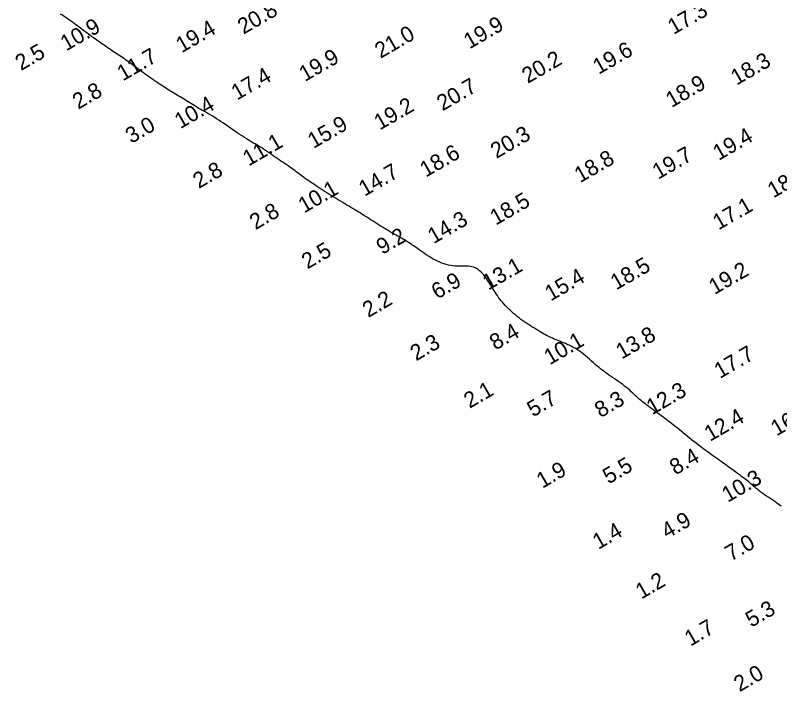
# Model space of a CAD drawing. Extents: x 3024098 to 3056816, y 418252 to 509144.
# Drawn here: x 3025732.3 to 3025973.9, y 428251.7 to 428465.6 of the extents above; entities that cross this region are included whole.
import ezdxf

# ---------------------------------------------------------------- set-up
doc = ezdxf.new("R2010")
doc.units = 0
doc.layers.add('V-CHAN-CONT-EL10', color=7, linetype='Continuous')
doc.layers.add('V-TOPO-SOUN-0911', color=7, linetype='Continuous')

msp = doc.modelspace()

# ---------------------------------------------------------------- linework, layer by layer
at = {"layer": 'V-CHAN-CONT-EL10'}
for points in [[(3025751.42, 428462.58), (3025750.91, 428462.96), (3025750.4, 428463.33), (3025749.87, 428463.71), (3025749.34, 428464.09), (3025748.8, 428464.46), (3025748.25, 428464.82), (3025747.7, 428465.18), (3025747.15, 428465.54), (3025746.59, 428465.88)], [(3025974.31, 428310.34), (3025973.87, 428310.68), (3025973.39, 428311.04), (3025972.87, 428311.42), (3025972.3, 428311.83), (3025971.68, 428312.24), (3025971.04, 428312.68), (3025970.39, 428313.12), (3025969.74, 428313.56), (3025969.1, 428313.99), (3025968.49, 428314.42), (3025967.91, 428314.84), (3025967.39, 428315.24), (3025966.91, 428315.62), (3025966.46, 428315.98), (3025966.04, 428316.34), (3025965.64, 428316.68), (3025965.26, 428317.02), (3025964.88, 428317.35), (3025964.49, 428317.68), (3025964.1, 428318.01), (3025963.69, 428318.34), (3025963.27, 428318.67), (3025962.85, 428319.01), (3025962.4, 428319.35), (3025961.95, 428319.69), (3025961.49, 428320.03), (3025961.02, 428320.38), (3025960.54, 428320.74), (3025960.04, 428321.1), (3025959.54, 428321.46), (3025959.03, 428321.83), (3025958.52, 428322.2), (3025957.99, 428322.57), (3025957.47, 428322.95), (3025956.94, 428323.33), (3025956.4, 428323.71), (3025955.87, 428324.09), (3025955.32, 428324.48), (3025954.76, 428324.89), (3025954.19, 428325.3), (3025953.6, 428325.72), (3025952.99, 428326.17), (3025952.35, 428326.63), (3025951.69, 428327.11), (3025951, 428327.6), (3025950.3, 428328.12), (3025949.59, 428328.65), (3025948.87, 428329.18), (3025948.14, 428329.73), (3025947.42, 428330.28), (3025946.7, 428330.84), (3025946, 428331.39), (3025945.31, 428331.95), (3025944.63, 428332.5), (3025943.97, 428333.04), (3025943.32, 428333.58), (3025942.68, 428334.1), (3025942.05, 428334.61), (3025941.44, 428335.1), (3025940.84, 428335.58), (3025940.25, 428336.04), (3025939.68, 428336.49), (3025939.11, 428336.92), (3025938.55, 428337.35), (3025938, 428337.76), (3025937.46, 428338.17), (3025936.93, 428338.57), (3025936.4, 428338.96), (3025935.88, 428339.35), (3025935.36, 428339.74), (3025934.85, 428340.12), (3025934.34, 428340.5), (3025933.84, 428340.87), (3025933.34, 428341.24), (3025932.85, 428341.6), (3025932.37, 428341.96), (3025931.89, 428342.31), (3025931.42, 428342.67), (3025930.96, 428343.02), (3025930.5, 428343.38), (3025930.05, 428343.74), (3025929.6, 428344.11), (3025929.17, 428344.5), (3025928.74, 428344.89), (3025928.31, 428345.29), (3025927.87, 428345.7), (3025927.43, 428346.13), (3025926.97, 428346.55), (3025926.49, 428346.99), (3025925.98, 428347.43), (3025925.44, 428347.88), (3025924.87, 428348.33), (3025924.26, 428348.78), (3025923.63, 428349.24), (3025922.98, 428349.69), (3025922.32, 428350.15), (3025921.66, 428350.6), (3025921, 428351.05), (3025920.36, 428351.49), (3025919.74, 428351.93), (3025919.13, 428352.37), (3025918.53, 428352.8), (3025917.94, 428353.25), (3025917.36, 428353.7), (3025916.78, 428354.17), (3025916.19, 428354.65), (3025915.6, 428355.16), (3025915, 428355.69), (3025914.38, 428356.24), (3025913.76, 428356.79), (3025913.13, 428357.35), (3025912.5, 428357.89), (3025911.86, 428358.42), (3025911.22, 428358.93), (3025910.57, 428359.4), (3025909.93, 428359.83), (3025909.28, 428360.22), (3025908.64, 428360.58), (3025908, 428360.91), (3025907.37, 428361.22), (3025906.75, 428361.5), (3025906.13, 428361.76), (3025905.52, 428362.01), (3025904.92, 428362.26), (3025904.33, 428362.49), (3025903.75, 428362.73), (3025903.18, 428362.96), (3025902.62, 428363.2), (3025902.05, 428363.45), (3025901.49, 428363.7), (3025900.94, 428363.97), (3025900.38, 428364.26), (3025899.82, 428364.55), (3025899.25, 428364.87), (3025898.69, 428365.19), (3025898.12, 428365.53), (3025897.54, 428365.88), (3025896.96, 428366.24), (3025896.37, 428366.6), (3025895.77, 428366.98), (3025895.16, 428367.36), (3025894.55, 428367.76), (3025893.93, 428368.16), (3025893.32, 428368.57), (3025892.71, 428369), (3025892.1, 428369.43), (3025891.5, 428369.88), (3025890.9, 428370.35), (3025890.32, 428370.82), (3025889.75, 428371.31), (3025889.19, 428371.8), (3025888.65, 428372.3), (3025888.13, 428372.8), (3025887.63, 428373.31), (3025887.15, 428373.81), (3025886.69, 428374.32), (3025886.25, 428374.82), (3025885.83, 428375.33), (3025885.43, 428375.85), (3025885.03, 428376.38), (3025884.65, 428376.92), (3025884.27, 428377.48), (3025883.89, 428378.06), (3025883.51, 428378.66), (3025883.13, 428379.28), (3025882.74, 428379.9), (3025882.35, 428380.53), (3025881.96, 428381.16), (3025881.56, 428381.77), (3025881.16, 428382.36), (3025880.75, 428382.92), (3025880.33, 428383.45), (3025879.9, 428383.95), (3025879.46, 428384.4), (3025879, 428384.81), (3025878.54, 428385.17), (3025878.07, 428385.47), (3025877.58, 428385.73), (3025877.09, 428385.92), (3025876.58, 428386.06), (3025876.05, 428386.15), (3025875.51, 428386.2), (3025874.95, 428386.22), (3025874.38, 428386.21), (3025873.79, 428386.2), (3025873.18, 428386.19), (3025872.56, 428386.2), (3025871.91, 428386.22), (3025871.25, 428386.27), (3025870.58, 428386.35), (3025869.89, 428386.45), (3025869.2, 428386.59), (3025868.5, 428386.75), (3025867.81, 428386.95), (3025867.11, 428387.19), (3025866.41, 428387.47), (3025865.72, 428387.78), (3025865.04, 428388.12), (3025864.36, 428388.48), (3025863.69, 428388.87), (3025863.04, 428389.27), (3025862.39, 428389.68), (3025861.76, 428390.11), (3025861.14, 428390.53), (3025860.54, 428390.96), (3025859.94, 428391.39), (3025859.36, 428391.81), (3025858.79, 428392.22), (3025858.22, 428392.63), (3025857.65, 428393.02), (3025857.09, 428393.4), (3025856.53, 428393.76), (3025855.97, 428394.1), (3025855.41, 428394.44), (3025854.85, 428394.76), (3025854.29, 428395.08), (3025853.73, 428395.4), (3025853.17, 428395.71), (3025852.6, 428396.03), (3025852.04, 428396.35), (3025851.47, 428396.68), (3025850.9, 428397.02), (3025850.32, 428397.36), (3025849.73, 428397.71), (3025849.14, 428398.07), (3025848.54, 428398.44), (3025847.93, 428398.82), (3025847.3, 428399.21), (3025846.67, 428399.61), (3025846.04, 428400.01), (3025845.41, 428400.42), (3025844.78, 428400.82), (3025844.15, 428401.22), (3025843.54, 428401.61), (3025842.95, 428401.99), (3025842.37, 428402.36), (3025841.8, 428402.72), (3025841.24, 428403.07), (3025840.69, 428403.41), (3025840.13, 428403.76), (3025839.56, 428404.1), (3025838.98, 428404.46), (3025838.37, 428404.82), (3025837.75, 428405.19), (3025837.1, 428405.57), (3025836.43, 428405.96), (3025835.75, 428406.37), (3025835.06, 428406.78), (3025834.36, 428407.19), (3025833.66, 428407.62), (3025832.96, 428408.04), (3025832.27, 428408.48), (3025831.58, 428408.91), (3025830.9, 428409.35), (3025830.23, 428409.78), (3025829.58, 428410.2), (3025828.94, 428410.62), (3025828.32, 428411.02), (3025827.73, 428411.41), (3025827.15, 428411.79), (3025826.6, 428412.15), (3025826.06, 428412.5), (3025825.54, 428412.84), (3025825.03, 428413.18), (3025824.53, 428413.53), (3025824.04, 428413.87), (3025823.55, 428414.22), (3025823.06, 428414.58), (3025822.58, 428414.95), (3025822.08, 428415.32), (3025821.59, 428415.7), (3025821.09, 428416.08), (3025820.59, 428416.46), (3025820.08, 428416.84), (3025819.55, 428417.22), (3025819.02, 428417.59), (3025818.48, 428417.97), (3025817.93, 428418.34), (3025817.37, 428418.71), (3025816.8, 428419.09), (3025816.23, 428419.47), (3025815.64, 428419.87), (3025815.04, 428420.28), (3025814.43, 428420.7), (3025813.82, 428421.13), (3025813.2, 428421.56), (3025812.59, 428421.99), (3025811.97, 428422.42), (3025811.37, 428422.84), (3025810.77, 428423.24), (3025810.18, 428423.62), (3025809.61, 428423.97), (3025809.05, 428424.3), (3025808.49, 428424.63), (3025807.94, 428424.94), (3025807.38, 428425.26), (3025806.81, 428425.58), (3025806.23, 428425.92), (3025805.64, 428426.28), (3025805.02, 428426.67), (3025804.38, 428427.08), (3025803.73, 428427.51), (3025803.06, 428427.96), (3025802.37, 428428.42), (3025801.67, 428428.91), (3025800.96, 428429.4), (3025800.24, 428429.9), (3025799.51, 428430.4), (3025798.78, 428430.9), (3025798.05, 428431.4), (3025797.32, 428431.9), (3025796.59, 428432.38), (3025795.87, 428432.85), (3025795.17, 428433.31), (3025794.48, 428433.74), (3025793.81, 428434.14), (3025793.15, 428434.53), (3025792.51, 428434.9), (3025791.89, 428435.25), (3025791.28, 428435.59), (3025790.69, 428435.92), (3025790.12, 428436.24), (3025789.55, 428436.57), (3025789, 428436.89), (3025788.47, 428437.22), (3025787.94, 428437.55), (3025787.42, 428437.87), (3025786.91, 428438.19), (3025786.41, 428438.51), (3025785.91, 428438.83), (3025785.41, 428439.13), (3025784.91, 428439.43), (3025784.41, 428439.73), (3025783.91, 428440.03), (3025783.41, 428440.32), (3025782.9, 428440.62), (3025782.39, 428440.92), (3025781.88, 428441.23), (3025781.35, 428441.55), (3025780.82, 428441.89), (3025780.29, 428442.23), (3025779.74, 428442.58), (3025779.19, 428442.95), (3025778.63, 428443.32), (3025778.06, 428443.7), (3025777.48, 428444.09), (3025776.9, 428444.48), (3025776.32, 428444.88), (3025775.73, 428445.29), (3025775.14, 428445.7), (3025774.54, 428446.11), (3025773.94, 428446.53), (3025773.35, 428446.95), (3025772.76, 428447.38), (3025772.17, 428447.8), (3025771.59, 428448.23), (3025771.02, 428448.66), (3025770.45, 428449.08), (3025769.89, 428449.5), (3025769.34, 428449.91), (3025768.8, 428450.3), (3025768.27, 428450.69), (3025767.75, 428451.06), (3025767.25, 428451.41), (3025766.76, 428451.75), (3025766.27, 428452.08), (3025765.79, 428452.4), (3025765.31, 428452.71), (3025764.83, 428453.03), (3025764.35, 428453.35), (3025763.86, 428453.67), (3025763.36, 428454), (3025762.85, 428454.35), (3025762.34, 428454.7), (3025761.82, 428455.05), (3025761.29, 428455.42), (3025760.75, 428455.79), (3025760.21, 428456.16), (3025759.67, 428456.54), (3025759.12, 428456.92), (3025758.58, 428457.3), (3025758.03, 428457.68), (3025757.48, 428458.07), (3025756.94, 428458.45), (3025756.4, 428458.84), (3025755.88, 428459.22), (3025755.36, 428459.6), (3025754.85, 428459.98), (3025754.36, 428460.35), (3025753.87, 428460.72), (3025753.38, 428461.09), (3025752.9, 428461.46), (3025752.41, 428461.83), (3025751.92, 428462.21), (3025751.42, 428462.58)]]:
    msp.add_lwpolyline(points, dxfattribs=at)

# ---------------------------------------------------------------- texts
at = {"layer": 'V-TOPO-SOUN-0911'}
for s, p in [('20.8 ', (3025804.37, 428459.4)), ('17.3 ', (3025940.32, 428459.31)), ('10.9 ', (3025748.36, 428454.12)), ('19.4 ', (3025784.85, 428453.53)), ('19.9 ', (3025875.82, 428454.75)), ('21.0 ', (3025847.72, 428451.79)), ('2.5', (3025734.08, 428447.9)), ('19.6 ', (3025916.64, 428446.71)), ('11.7 ', (3025766.28, 428444.64)), ('19.9 ', (3025823.79, 428444.44)), ('20.2 ', (3025894.23, 428443.85)), ('18.3 ', (3025960.24, 428443.3)), ('17.4 ', (3025802.37, 428438.57)), ('20.7 ', (3025867.33, 428435.19)), ('18.9 ', (3025939.7, 428436.21)), ('2.8', (3025752.17, 428435.69)), ('10.4 ', (3025784.42, 428429.52)), ('19.2 ', (3025847.48, 428429.12)), ('3.0', (3025768.92, 428424.86)), ('15.9 ', (3025826.51, 428423.28)), ('20.3 ', (3025884.32, 428420.1)), ('11.1 ', (3025805.99, 428417.72)), ('19.4 ', (3025954.6, 428419.51)), ('18.6 ', (3025861.98, 428414.2)), ('18.8 ', (3025910.8, 428412.46)), ('19.7 ', (3025935.47, 428413.54)), ('2.8', (3025790.26, 428410.62)), ('14.7 ', (3025842.65, 428408.16)), ('18.9 ', (3025971.85, 428407.63)), ('10.1 ', (3025823.54, 428402.86)), ('18.5 ', (3025884.15, 428399.04)), ('2.8', (3025808.17, 428397.6)), ('17.1 ', (3025954.55, 428397.54)), ('14.3 ', (3025864.47, 428393.16)), ('9.2', (3025848.23, 428389.76)), ('2.5', (3025824.6, 428385.17)), ('18.5 ', (3025922.2, 428378.56)), ('13.1 ', (3025881.78, 428378.51)), ('19.2 ', (3025953.28, 428377.12)), ('6.9', (3025865.62, 428375.65)), ('15.4 ', (3025901.48, 428375.05)), ('2.2', (3025843.83, 428369.84)), ('8.4', (3025884.02, 428359.54)), ('10.1 ', (3025901.2, 428354.89)), ('13.8 ', (3025923.92, 428356.68)), ('2.3', (3025858.93, 428356.13)), ('17.7 ', (3025954.99, 428350.58)), ('2.1', (3025875.87, 428341.15)), ('12.3 ', (3025933.57, 428339.1)), ('5.7', (3025895.87, 428338.41)), ('8.3', (3025917.23, 428338.18)), ('12.4 ', (3025951.87, 428330.7)), ('16.5 ', (3025972.89, 428332.4)), ('8.4', (3025940.91, 428320.07)), ('1.9', (3025898.85, 428315.84)), ('5.5', (3025919.78, 428317.22)), ('10.3 ', (3025957.42, 428311.41)), ('4.9', (3025938.29, 428299.93)), ('1.4', (3025916.57, 428296.55)), ('7.0', (3025958.45, 428292.81)), ('1.2', (3025930.15, 428280.84)), ('5.3', (3025964.9, 428271.91)), ('1.7', (3025945.64, 428265.94)), ('2.0', (3025961.21, 428251.54))]:
    msp.add_text(s, height=5, rotation=30, dxfattribs=at).set_placement(p)

doc.saveas('drawing.dxf')
